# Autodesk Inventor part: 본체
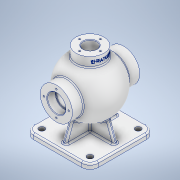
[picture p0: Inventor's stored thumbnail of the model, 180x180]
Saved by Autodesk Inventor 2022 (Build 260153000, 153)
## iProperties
Created: 2024-04
Part Number: 본체
Material: 알루미늄 6061
Document SubType Name: Modeling
Designer: user
Mass: 1526.72 g
Surface Area: 1173.82 cm^2
Volume: 565.453 cm^3
Density: 2.7 g/cm^3
Appearance: 알루미늄 - 평지
Author: user
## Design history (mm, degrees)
sketch "스케치1"
  geometry: L1 (-75.6, 0)-(75.6, 0) reference; L2 (0, -10.8)-(0, 64.8) reference; L3 (-54, 0)-(54, 0); A1 r 54 centre (0, 0) between (54, 0) and (-54, 0); 1 further point
  constraints: 2 end point, 2 point on circle, 2 point on line, 1 centre point, 1 coincident, 1 collinear
  dimensions: "d0" = 54 radius of A1
revolve "회전1" sketch "스케치1" stored, may be unused: angle "d1" = 360 deg
node "작업 평면1"
sketch "스케치2"
  geometry: L1 (62.5, -62.5)-(-62.5, -62.5); L2 (-62.5, -62.5)-(-62.5, 62.5); L3 (-62.5, 62.5)-(62.5, 62.5); L4 (62.5, 62.5)-(62.5, -62.5); L5 (62.5, -62.5)-(-62.5, 62.5); L6 (-62.5, -62.5)-(62.5, 62.5); 1 further point
  constraints: 12 end point, 2 midpoint, 2 parallel, 1 horizontal, 1 perpendicular
  dimensions: "d3" = 125 distance of L3.end L1.start; "d4" = 125 distance of L2.end L3.end
extrude "돌출1" join sketch "스케치2" distance "d5" = 10; taper "d6" = 0 deg
sketch "스케치3"
  geometry: L1 (-75, 62.5)-(-75, -62.5) reference; L2 (-75, -50.5)-(-15.987, -29.021); L3 (-15.987, -29.021)-(-15.987, 29.021); L4 (-15.987, 29.021)-(-75, 50.5); L5 (-112.8, 0)-(81.8, 0) reference; L6 (0, -87.5)-(0, 87.5) reference; L7 (-85, -62.5)-(-75, -62.5) reference; L8 (-75, -50.5)-(-75, 50.5); 1 further point
  constraints: 8 end point, 2 point on line, 1 collinear, 1 parallel, 1 other
  dimensions: "d7" = 12 distance from line of L7 L2.start; "d8" = 20 deg angle of L7 L2; "d9" = 58.04193 distance of L2.end L3.end
extrude "돌출2" join sketch "스케치3" stored distance "d10" = 8; taper "d11" = 0 deg
sketch "스케치4"
  geometry: L1 (62.5, -75)-(-62.5, -75) reference; L2 (-50.5, -75)-(-31.702, -23.353); L3 (-31.702, -23.353)-(31.702, -23.353); L4 (31.702, -23.353)-(50.5, -75); L5 (-87.5, 0)-(87.5, 0) reference; L6 (0, -112.8)-(0, 81.8) reference; L7 (-62.5, -85)-(-62.5, -75) reference; 1 further point
  constraints: 6 end point, 2 point on line, 1 parallel, 1 other
  dimensions: "d12" = 20 deg angle of L7 L2; "d13" = 12 distance from line of L7 L2.start; "d14" = 63.40414 distance of L2.end L3.end
extrude "돌출3" join sketch "스케치4" stored distance "d15" = 8; taper "d16" = 0 deg
node "작업 평면2"
sketch "스케치5"
  geometry: C1 r 27 at (0, 0); 1 further point
  constraints: 1 centre point, 1 coincident
  dimensions: "d18" = 54 diameter of C1
extrude "돌출4" join sketch "스케치5" stored distance "d19" = 8; taper "d20" = 0 deg
sketch "스케치6"
  geometry: L1 (-115, 0)-(95, 0) reference; L2 (0, -87.5)-(0, 87.5) reference; L3 (0, 65)-(31, 65); L4 (31, 65)-(31, -65); L5 (31, -65)-(0, -65); L6 (0, -65)-(0, 65); 2 further points
  constraints: 8 end point, 2 parallel, 1 horizontal, 1 perpendicular, 1 point on line, 1 other
  dimensions: "d21" = 62 diameter of L4 L2; "d22" = 130 distance of L3.end L4.end
revolve "회전2" sketch "스케치6" stored, may be unused: angle "d23" = 360 deg
sketch "스케치7"
  geometry: L1 (0, -91)-(0, 91) reference; L2 (-115, 0)-(95, 0) reference; L3 (0, 44)-(0, -44); A1 r 44 centre (0, 0) between (0, -44) and (0, 44); 1 further point
  constraints: 2 end point, 2 point on circle, 2 point on line, 1 centre point, 1 coincident, 1 collinear
  dimensions: "d24" = 44 radius of A1
revolve "회전3" sketch "스케치7" stored, may be unused: angle "d25" = 360 deg
sketch "스케치8"
  geometry: 1 further point
sketch "스케치9"
  geometry: C1 r 17.5 at (0, 0); 1 further point
  constraints: 1 centre point, 1 coincident
  dimensions: "d26" = 35 diameter of C1
extrude "돌출5" cut sketch "스케치9" distance "d27" = 16; taper "d28" = 0 deg
sketch "스케치10"
  geometry: C1 r 15 at (0, 0); 1 further point
  constraints: 1 centre point, 1 coincident
  dimensions: "d29" = 30 diameter of C1
extrude "돌출6" cut sketch "스케치10" extent not by distance; stored distance "d30" = 0; taper "d31" = 0 deg
sketch "스케치11"
  geometry: C1 r 13 at (0, 0); 1 further point
  constraints: 1 centre point, 1 coincident
  dimensions: "d32" = 26 diameter of C1
extrude "돌출7" cut sketch "스케치11" stored distance "d33" = 10; taper "d34" = 0 deg
sketch "스케치12"
  geometry: L1 (0, -115)-(0, 95) reference; L2 (-87.5, 0)-(87.5, 0) reference; 2 further points
  constraints: 1 point on line
  dimensions: "d35" = 48 diameter of point (0, 24) L2
hole "구멍1" sketch "스케치12" at (0, 24) diameter "d36" = 3.242; stored, may be unused: countersink angle "d40" = 90 deg, drill point angle "d42" = 118 deg; dims "d37" = 12, "d38" = 4, "d39" = 2, "d41" = 15
sketch "스케치13"
  geometry: L1 (-87.5, 0)-(87.5, 0) reference; L2 (0, 91)-(0, -91) reference; 2 further points
  constraints: 1 point on line
  dimensions: "d46" = 40 diameter of point (-20, 0) L2
hole "구멍2" sketch "스케치13" at (-20, 0) diameter "d47" = 3.242; stored, may be unused: countersink angle "d51" = 90 deg, drill point angle "d53" = 118 deg; dims "d48" = 9, "d49" = 4, "d50" = 2, "d52" = 11
fillet "모깎기1" dims "d57" = 16
sketch "스케치14"
  geometry: L1 (-62.5, 46.5)-(-62.5, -46.5) reference; L2 (46.5, 62.5)-(-46.5, 62.5) reference; L3 (62.5, -46.5)-(62.5, 46.5) reference; L4 (-46.5, -62.5)-(46.5, -62.5) reference; A1 r 16 centre (-46.5, -46.5) between (-62.5, -46.5) and (-46.5, -62.5) reference; A2 r 16 centre (-46.5, 46.5) between (-46.5, 62.5) and (-62.5, 46.5) reference; A3 r 16 centre (46.5, 46.5) between (62.5, 46.5) and (46.5, 62.5) reference; A4 r 16 centre (46.5, -46.5) between (46.5, -62.5) and (62.5, -46.5) reference; 5 further points
  constraints: 4 coincident
hole "구멍3" sketch "스케치14" at (-46.5, -46.5), (-46.5, 46.5), (46.5, 46.5), (46.5, -46.5) diameter "d58" = 11; stored, may be unused: countersink angle "d62" = 90 deg, drill point angle "d64" = 118 deg; dims "d59" = 9, "d60" = 4, "d61" = 2, "d63" = 11
chamfer "모따기1" distance "d65" = 1; stored, may be unused: second distance "d66" = 2, angle "d67" = 45 deg
fillet "모깎기2" dims "d68" = 0.6
fillet "모깎기3" dims "d69" = 3
fillet "모깎기4" dims "d70" = 3
fillet "모깎기5" dims "d71" = 3
fillet "모깎기6" dims "d72" = 3
fillet "모깎기7" dims "d73" = 3
node "작업 평면3"
sketch "스케치15"
  geometry: L1 (65, 27)-(65, -27) reference; L2 (-115, 0)-(95, 0) reference; 2 further points
  constraints: 1 point on line, 1 other
  dimensions: "d75" = 9 distance from line of L1 point (56, 0)
feature "엠보싱1" sketch "스케치15" dims "d7" = 12, "d8" = 20 deg, "d9" = 58.04193, "d76" = 0.5, "d77" = 0
node "솔리드1"
mirror "미러1"
pattern_circular "원형 패턴1" dims angle "d44" = 360 deg
mirror "미러2"
pattern_circular "원형 패턴2" dims angle "d55" = 360 deg
node "투영된 루프1"
feature "A9D066F2-1C7D-4E18-AEED-F7BC21143FA4" dims "d58" = 11, "d59" = 9, "d60" = 4, "d61" = 2, "d62" = 90 deg, "d63" = 11, "d64" = 118 deg
other parameters: "d2" = -85, "d74" = -66.25
